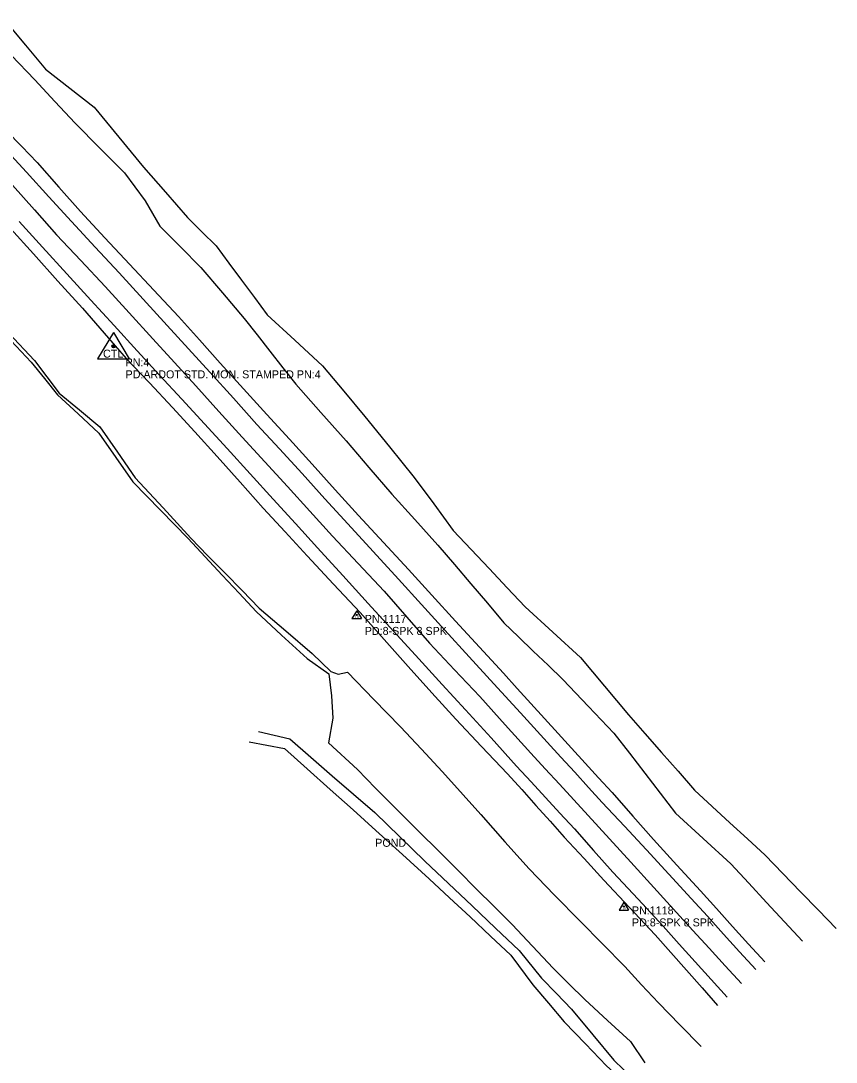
# Model space of a CAD drawing. Extents: x 1193883 to 1197064, y 1474583 to 1477379.
# Drawn here: x 1195807 to 1196316, y 1475221 to 1475871 of the extents above; entities that cross this region are included whole.
import ezdxf

# ---------------------------------------------------------------- set-up
doc = ezdxf.new("R2010")
doc.units = 0
for name, color, linetype in [('S_DITCHLINE', 7, 'Continuous'), ('S_EDGE_PAVEMENT', 7, 'Continuous'), ('S_LEVEE', 7, 'Continuous'), ('S_MSC_PT_SYM', 7, 'Continuous'), ('S_PAVEMENT_CROWN', 7, 'Continuous'), ('S_PRIMARY_CTL', 7, 'Continuous'), ('S_PRIMARY_CTL_ANNOT', 7, 'Continuous'), ('S_SECONDARY_CTL', 7, 'Continuous'), ('S_SECONDARY_CTL_ANNOT', 7, 'Continuous'), ('S_SHOULDER', 7, 'Continuous'), ('S_SURVEY_TEXT_ANNOT', 7, 'Continuous')]:
    doc.layers.add(name, color=color, linetype=linetype)

msp = doc.modelspace()

# ---------------------------------------------------------------- linework, layer by layer
at = {"layer": 'S_DITCHLINE'}
for points in [[(1195797.47, 1475871.27), (1195810.02, 1475856.16), (1195822.56, 1475841.05), (1195837.76, 1475829.17), (1195852.96, 1475817.29), (1195868.35, 1475798.61), (1195883.74, 1475779.93), (1195897.52, 1475764.21), (1195911.3, 1475748.49), (1195920.2, 1475739.58), (1195929.11, 1475730.67), (1195937.08, 1475719.94), (1195945.05, 1475709.21), (1195953.02, 1475698.48), (1195960.99, 1475687.75), (1195978.29, 1475671.77), (1195995.6, 1475655.78), (1196008.78, 1475639.93), (1196021.96, 1475624.07), (1196037.39, 1475605.11), (1196052.82, 1475586.15), (1196065.03, 1475569.59), (1196077.23, 1475553.03), (1196088.44, 1475541.08), (1196099.65, 1475529.13), (1196110.87, 1475517.18), (1196122.08, 1475505.23), (1196139.32, 1475489.42), (1196156.57, 1475473.62), (1196171.6, 1475455.72), (1196186.62, 1475437.83), (1196196.94, 1475426.08), (1196207.26, 1475414.33), (1196217.58, 1475402.58), (1196227.9, 1475390.83), (1196238.91, 1475380.65), (1196249.92, 1475370.48), (1196260.93, 1475360.3), (1196271.93, 1475350.12), (1196283.03, 1475338.67), (1196294.13, 1475327.22), (1196305.23, 1475315.77), (1196316.32, 1475304.32)], [(1195801.09, 1475849.92), (1195815.97, 1475834.37), (1195828.48, 1475820.85), (1195840.99, 1475807.32), (1195856.42, 1475791.84), (1195871.85, 1475776.36), (1195884.7, 1475758.88), (1195894.01, 1475742.94), (1195906.77, 1475730.13), (1195919.54, 1475717.31), (1195933.09, 1475701.32), (1195946.64, 1475685.34), (1195954.69, 1475675.1), (1195962.75, 1475664.86), (1195970.8, 1475654.62), (1195978.86, 1475644.38), (1195994.58, 1475626.68), (1196010.29, 1475608.99), (1196024.58, 1475592.34), (1196038.87, 1475575.69), (1196053.22, 1475559.76), (1196067.57, 1475543.84), (1196077.88, 1475531.72), (1196088.18, 1475519.59), (1196098.48, 1475507.47), (1196108.79, 1475495.34), (1196117.99, 1475486.49), (1196127.18, 1475477.64), (1196136.38, 1475468.79), (1196145.58, 1475459.94), (1196161.56, 1475443.11), (1196177.55, 1475426.29), (1196187.17, 1475413.8), (1196196.8, 1475401.32), (1196206.42, 1475388.84), (1196216.05, 1475376.35), (1196233.28, 1475360.6), (1196250.51, 1475344.84), (1196261.68, 1475332.74), (1196272.85, 1475320.65), (1196284.03, 1475308.55), (1196295.2, 1475296.46)], [(1195799.59, 1475676.3), (1195815.65, 1475659.07), (1195823.41, 1475648.89), (1195831.17, 1475638.71), (1195843.8, 1475628.26), (1195856.43, 1475617.8), (1195867.53, 1475601.88), (1195878.62, 1475585.95), (1195887.31, 1475576.49), (1195896, 1475567.02), (1195904.69, 1475557.56), (1195913.38, 1475548.1), (1195924.03, 1475537.2), (1195934.68, 1475526.3), (1195945.33, 1475515.39), (1195955.98, 1475504.49), (1195972.56, 1475490.31), (1195989.14, 1475476.14), (1196000.78, 1475464.9), (1196005.32, 1475463.28), (1196011.16, 1475464.42), (1196027.7, 1475447.35), (1196044.23, 1475430.29), (1196057.3, 1475416.41), (1196070.37, 1475402.53), (1196072.32, 1475400.09), (1196083.34, 1475387.86), (1196094.37, 1475375.64), (1196109.45, 1475358.61), (1196124.53, 1475341.58), (1196140.44, 1475325.27), (1196156.35, 1475308.96), (1196170.33, 1475294.77), (1196184.31, 1475280.58), (1196194.8, 1475269.26), (1196205.3, 1475257.94), (1196218.61, 1475244.27), (1196231.92, 1475230.6)], [(1195797.91, 1475674.83), (1195813.65, 1475658.16), (1195821.85, 1475647.95), (1195830.05, 1475637.74), (1195842.95, 1475625.77), (1195855.85, 1475613.8), (1195866.51, 1475598.62), (1195877.17, 1475583.44), (1195894.38, 1475565.72), (1195911.59, 1475548), (1195922.2, 1475536.57), (1195932.8, 1475525.14), (1195943.41, 1475513.72), (1195954.02, 1475502.29), (1195969.95, 1475487.6), (1195985.89, 1475472.92), (1195999.6, 1475463.41), (1196001.16, 1475449.65), (1196002.05, 1475435.65), (1195999.21, 1475420.43), (1196017.43, 1475403.65), (1196028.71, 1475392.1), (1196040, 1475380.54), (1196054.61, 1475366.04), (1196069.22, 1475351.54), (1196080.4, 1475340.38), (1196091.59, 1475329.22), (1196102.78, 1475318.05), (1196113.96, 1475306.89), (1196126.78, 1475293.27), (1196139.59, 1475279.65), (1196149.45, 1475269.81), (1196159.31, 1475259.98), (1196173.61, 1475246.88), (1196187.91, 1475233.79), (1196196.86, 1475220.48)]]:
    msp.add_lwpolyline(points, dxfattribs=at)
at = {"layer": 'S_EDGE_PAVEMENT'}
for points in [[(1195801.18, 1475787.19), (1195810.67, 1475776.75), (1195824.68, 1475761.34), (1195838.7, 1475745.94), (1195853.61, 1475729.86), (1195868.52, 1475713.78), (1195883.5, 1475697.37), (1195898.49, 1475680.96), (1195911.85, 1475666.43), (1195925.2, 1475651.91), (1195939.9, 1475635.58), (1195954.6, 1475619.25), (1195968.68, 1475603.86), (1195982.77, 1475588.46), (1195997.01, 1475572.76), (1196011.26, 1475557.06), (1196027.14, 1475539.8), (1196043.01, 1475522.54), (1196057.44, 1475506.67), (1196071.87, 1475490.8), (1196087.23, 1475474.03), (1196102.6, 1475457.26), (1196119.22, 1475439.04), (1196135.85, 1475420.81), (1196144.43, 1475411.39), (1196153.02, 1475401.96), (1196161.6, 1475392.54), (1196170.18, 1475383.11), (1196184.07, 1475368.31), (1196197.97, 1475353.52), (1196211.88, 1475338.32), (1196225.8, 1475323.13), (1196235.88, 1475312.03), (1196245.95, 1475300.94), (1196256.03, 1475289.84), (1196266.11, 1475278.74)], [(1195806.07, 1475745.87), (1195820.75, 1475729.84), (1195835.85, 1475713.32), (1195850.96, 1475696.81), (1195865.42, 1475681), (1195879.88, 1475665.19), (1195893.83, 1475650.04), (1195907.77, 1475634.89), (1195921.84, 1475619.48), (1195935.91, 1475604.07), (1195950.32, 1475588.29), (1195964.73, 1475572.52), (1195978.62, 1475557.32), (1195992.51, 1475542.13), (1196008.3, 1475524.75), (1196024.09, 1475507.37), (1196039.88, 1475490.04), (1196055.67, 1475472.71), (1196070.27, 1475456.81), (1196084.86, 1475440.91), (1196100.8, 1475423.38), (1196116.75, 1475405.85), (1196125.77, 1475396.07), (1196134.8, 1475386.28), (1196143.82, 1475376.49), (1196152.85, 1475366.71), (1196164.88, 1475353.13), (1196176.91, 1475339.56), (1196192.58, 1475322.65), (1196208.24, 1475305.74), (1196218.24, 1475294.66), (1196228.23, 1475283.58), (1196238.22, 1475272.5), (1196248.21, 1475261.42)]]:
    msp.add_lwpolyline(points, dxfattribs=at)
at = {"layer": 'S_LEVEE'}
for points in [[(1195955.49, 1475427.34), (1195975.08, 1475422.83), (1195988.36, 1475411.3), (1196001.63, 1475399.78), (1196014.9, 1475388.26), (1196028.18, 1475376.74), (1196043.86, 1475361.63), (1196059.55, 1475346.53), (1196074.25, 1475332.56), (1196088.95, 1475318.59), (1196103.65, 1475304.61), (1196118.35, 1475290.64), (1196132.33, 1475273.31), (1196141.65, 1475263.7), (1196150.96, 1475254.09), (1196164.27, 1475238.07), (1196177.57, 1475222.06), (1196189.62, 1475210.47), (1196201.68, 1475198.87)], [(1195949.77, 1475420.93), (1195971.77, 1475416.9), (1195986.05, 1475404.09), (1196000.33, 1475391.29), (1196014.61, 1475378.48), (1196028.89, 1475365.67), (1196045.52, 1475350.5), (1196062.16, 1475335.32), (1196074.91, 1475323.44), (1196087.67, 1475311.57), (1196100.42, 1475299.7), (1196113.18, 1475287.82), (1196126.79, 1475269.21), (1196136.66, 1475257.69), (1196146.53, 1475246.17), (1196159.72, 1475232.39), (1196172.91, 1475218.6), (1196184.09, 1475208.47), (1196195.27, 1475198.34)]]:
    msp.add_lwpolyline(points, dxfattribs=at)
at = {"layer": 'S_MSC_PT_SYM'}
msp.add_lwpolyline([(1196028.48, 1475360.41), (1196028.48, 1475360.46), (1196028.48, 1475360.41), (1196028.43, 1475360.41), (1196028.48, 1475360.41), (1196028.48, 1475360.36), (1196028.48, 1475360.41), (1196028.53, 1475360.41)], dxfattribs=at)
at = {"layer": 'S_PAVEMENT_CROWN'}
msp.add_lwpolyline([(1195802.04, 1475768.56), (1195815.78, 1475753.12), (1195829.51, 1475737.68), (1195844.63, 1475721.48), (1195859.76, 1475705.28), (1195874.72, 1475688.92), (1195889.69, 1475672.56), (1195903.04, 1475657.94), (1195916.38, 1475643.33), (1195930.89, 1475627.3), (1195945.4, 1475611.28), (1195959.53, 1475595.9), (1195973.66, 1475580.52), (1195987.71, 1475564.98), (1196001.76, 1475549.45), (1196017.86, 1475532.3), (1196033.96, 1475515.14), (1196048.15, 1475498.87), (1196062.35, 1475482.6), (1196078.04, 1475465.91), (1196093.74, 1475449.22), (1196109.68, 1475431.55), (1196125.62, 1475413.88), (1196134.6, 1475404.16), (1196143.58, 1475394.44), (1196152.56, 1475384.72), (1196161.55, 1475375), (1196174.83, 1475360.38), (1196188.11, 1475345.76), (1196202.37, 1475330.03), (1196216.63, 1475314.3), (1196226.77, 1475303.23), (1196236.91, 1475292.16), (1196247.04, 1475281.1), (1196257.18, 1475270.03)], dxfattribs=at)
at = {"layer": 'S_PRIMARY_CTL'}
for p, q in [((1195865.07, 1475676.68), (1195855.04, 1475660.16)), ((1195865.07, 1475676.68), (1195874.9, 1475660.16)), ((1195855.04, 1475660.16), (1195874.9, 1475660.16))]:
    msp.add_line(p, q, dxfattribs=at)
for radius in [1.04, 0.609, 0.344]:
    msp.add_circle((1195865.07, 1475667.98), radius, dxfattribs=at)
at = {"layer": 'S_SECONDARY_CTL'}
for p, q in [((1196016.96, 1475502.86), (1196013.95, 1475497.9)), ((1196016.96, 1475502.86), (1196019.91, 1475497.9)), ((1196013.95, 1475497.9), (1196019.91, 1475497.9)), ((1196183.79, 1475320.8), (1196180.78, 1475315.85)), ((1196183.79, 1475320.8), (1196186.73, 1475315.85)), ((1196180.78, 1475315.85), (1196186.73, 1475315.85))]:
    msp.add_line(p, q, dxfattribs=at)
for centre, radius in [((1196016.96, 1475500.25), 0.311), ((1196016.96, 1475500.25), 0.183), ((1196016.96, 1475500.25), 0.103), ((1196183.79, 1475318.19), 0.311), ((1196183.79, 1475318.19), 0.183), ((1196183.79, 1475318.19), 0.103)]:
    msp.add_circle(centre, radius, dxfattribs=at)
at = {"layer": 'S_SHOULDER'}
for points in [[(1195798.26, 1475802.54), (1195807.77, 1475792.68), (1195817.29, 1475782.82), (1195830.82, 1475767.46), (1195844.36, 1475752.1), (1195859.66, 1475735.74), (1195874.96, 1475719.39), (1195890.29, 1475703.03), (1195905.61, 1475686.68), (1195918.63, 1475672.03), (1195931.65, 1475657.37), (1195946.26, 1475641.39), (1195960.88, 1475625.42), (1195975.01, 1475609.92), (1195989.15, 1475594.42), (1196003.55, 1475578.4), (1196017.95, 1475562.37), (1196033.57, 1475545.53), (1196049.2, 1475528.68), (1196063.92, 1475512.48), (1196078.64, 1475496.28), (1196093.65, 1475480.02), (1196108.66, 1475463.77), (1196117.15, 1475454.38), (1196125.64, 1475445), (1196134.13, 1475435.61), (1196142.62, 1475426.22), (1196151.07, 1475416.98), (1196159.52, 1475407.73), (1196167.97, 1475398.48), (1196176.42, 1475389.24), (1196189.37, 1475374.56), (1196202.32, 1475359.88), (1196216.92, 1475343.86), (1196231.52, 1475327.85), (1196241.56, 1475316.78), (1196251.6, 1475305.72), (1196261.65, 1475294.65), (1196271.69, 1475283.58)], [(1195800.63, 1475741.61), (1195815.02, 1475725.65), (1195830.3, 1475708.76), (1195845.58, 1475691.87), (1195859.29, 1475676.14), (1195873, 1475660.42), (1195887.48, 1475645.14), (1195901.96, 1475629.86), (1195915.91, 1475614.55), (1195929.86, 1475599.23), (1195944.13, 1475583.06), (1195958.41, 1475566.89), (1195972.19, 1475552.05), (1195985.96, 1475537.2), (1196002.48, 1475519.43), (1196019, 1475501.67), (1196034, 1475484.82), (1196048.99, 1475467.97), (1196063.91, 1475451.5), (1196078.82, 1475435.02), (1196094.94, 1475418), (1196111.07, 1475400.99), (1196119.93, 1475391.12), (1196128.8, 1475381.25), (1196137.66, 1475371.37), (1196146.53, 1475361.5), (1196158.9, 1475348.04), (1196171.27, 1475334.57), (1196187.27, 1475317.49), (1196203.26, 1475300.41), (1196213.02, 1475289.4), (1196222.78, 1475278.4), (1196232.54, 1475267.4), (1196242.3, 1475256.39)]]:
    msp.add_lwpolyline(points, dxfattribs=at)

# ---------------------------------------------------------------- texts
at = {"layer": 'S_PRIMARY_CTL'}
msp.add_text('CTL', height=5, rotation=360, dxfattribs=at).set_placement((1195858.49, 1475660.9))
at = {"layer": 'S_PRIMARY_CTL_ANNOT'}
for s, p in [('PN:4', (1195872.57, 1475655.48)), ('PD:ARDOT STD. MON. STAMPED PN:4', (1195872.57, 1475647.98))]:
    msp.add_text(s, height=5, dxfattribs=at).set_placement(p)
at = {"layer": 'S_SECONDARY_CTL'}
for p in [(1196015.76, 1475498.23), (1196182.58, 1475316.18)]:
    msp.add_text('TV', height=1.5, rotation=360, dxfattribs=at).set_placement(p)
at = {"layer": 'S_SECONDARY_CTL_ANNOT'}
for s, p in [('PN:1117', (1196021.96, 1475495.25)), ('PD:8-SPK 8 SPK', (1196021.96, 1475487.75)), ('PN:1118', (1196188.79, 1475313.19)), ('PD:8-SPK 8 SPK', (1196188.79, 1475305.69))]:
    msp.add_text(s, height=5, dxfattribs=at).set_placement(p)
at = {"layer": 'S_SURVEY_TEXT_ANNOT'}
msp.add_text('POND', height=5, dxfattribs=at).set_placement((1196028.48, 1475355.41))

doc.saveas('drawing.dxf')
